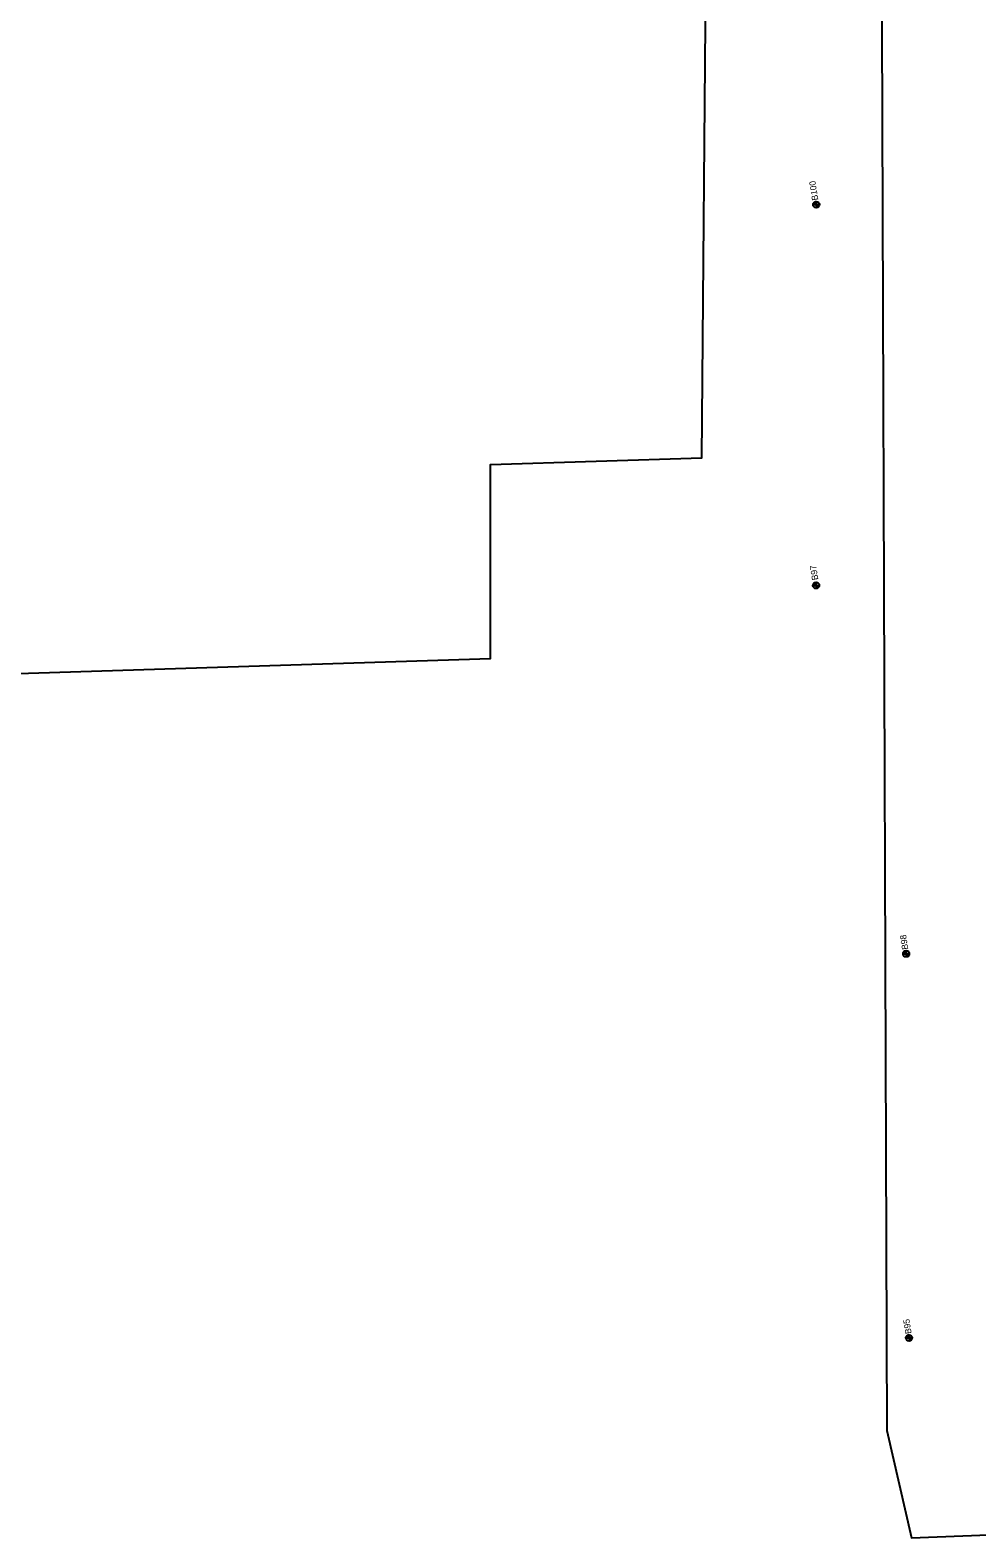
# Model space of a CAD drawing. Extents: x 331323 to 388339, y 121519 to 205315.
# Drawn here: x 354755 to 356257, y 180308 to 182703 of the extents above; entities that cross this region are included whole.
import ezdxf

# ---------------------------------------------------------------- set-up
doc = ezdxf.new("R2010")
doc.units = 0
for name, color, linetype in [('E_SOIL_BORE1 [KAPUR_CADDS_LEVELS]', 7, 'Continuous'), ('E_SOIL_BORE2 [KAPUR_CADDS_LEVELS]', 7, 'Continuous'), ('Level 21', 7, 'Continuous'), ('P_MARK', 7, 'Continuous')]:
    doc.layers.add(name, color=color, linetype=linetype)

msp = doc.modelspace()

# ---------------------------------------------------------------- linework, layer by layer
at = {"layer": 'Level 21'}
for points in [[(356105.1, 183006.3), (356114.3, 180479.1), (356153.7, 180308.5), (356397.8, 180318.1)], [(353557.1, 182916.5), (353547.6, 182701.3), (353533.4, 182581.6), (353525.2, 182506.3), (353462.8, 182406.1), (353416.3, 182333.8), (353341.3, 182220), (353327.7, 182131.7), (353320.6, 182067.3), (353306.1, 181966.7), (353328.2, 181715.1), (353337, 181619.1), (353349.1, 181504.5), (353365.8, 181335.5), (353376.4, 181288.1), (353386.3, 181245), (353405.7, 181167), (354162.4, 181174.2), (354327.4, 181348.1), (354335.3, 181668.3), (355485.3, 181704.9), (355485.4, 182013), (355820.8, 182023.7), (355827.8, 182838.2)]]:
    msp.add_lwpolyline(points, dxfattribs=at)
at = {"layer": 'P_MARK'}
for p, q in [((356002.3, 182430.8), (356002.3, 182420.8)), ((355997.3, 182425.8), (356007.3, 182425.8)), ((355997.1, 181821), (356007.1, 181821)), ((356002.1, 181826), (356002.1, 181816)), ((356140, 181236), (356150, 181236)), ((356145, 181241), (356145, 181231)), ((356149.6, 180631), (356149.6, 180621)), ((356144.6, 180626), (356154.6, 180626))]:
    msp.add_line(p, q, dxfattribs=at)
for centre in [(356002.3, 182425.8), (356002.1, 181821), (356145, 181236), (356149.6, 180626)]:
    msp.add_circle(centre, 5, dxfattribs=at)
for centre, radius, start, end in [((356002.3, 182425.8), 4.5, 89.9869, 179.9869), ((356002.3, 182425.8), 4, 89.9869, 179.9869), ((356002.3, 182425.8), 3.5, 89.9869, 179.9869), ((356002.3, 182425.8), 3, 89.9869, 179.9869), ((356002.3, 182425.8), 2.5, 89.9869, 179.9869), ((356002.3, 182425.8), 2, 89.9869, 179.9869), ((356002.3, 182425.8), 1.5, 89.9869, 179.9869), ((356002.3, 182425.8), 1, 89.9869, 179.9869), ((356002.3, 182425.8), 0.5, 89.9869, 179.9869), ((356002.3, 182425.8), 4.5, 269.9869, 359.9869), ((356002.3, 182425.8), 4, 269.9869, 359.9869), ((356002.3, 182425.8), 3.5, 269.9869, 359.9869), ((356002.3, 182425.8), 3, 269.9869, 359.9869), ((356002.3, 182425.8), 2.5, 269.9869, 359.9869), ((356002.3, 182425.8), 2, 269.9869, 359.9869), ((356002.3, 182425.8), 1.5, 269.9869, 359.9869), ((356002.3, 182425.8), 1, 269.9869, 359.9869), ((356002.3, 182425.8), 0.5, 269.9869, 359.9869), ((356002.1, 181821), 4.5, 89.9869, 179.9869), ((356002.1, 181821), 4, 89.9869, 179.9869), ((356002.1, 181821), 3.5, 89.9869, 179.9869), ((356002.1, 181821), 3, 89.9869, 179.9869), ((356002.1, 181821), 2.5, 89.9869, 179.9869), ((356002.1, 181821), 2, 89.9869, 179.9869), ((356002.1, 181821), 1.5, 89.9869, 179.9869), ((356002.1, 181821), 1, 89.9869, 179.9869), ((356002.1, 181821), 0.5, 89.9869, 179.9869), ((356002.1, 181821), 4.5, 269.9869, 359.9869), ((356002.1, 181821), 4, 269.9869, 359.9869), ((356002.1, 181821), 3.5, 269.9869, 359.9869), ((356002.1, 181821), 3, 269.9869, 359.9869), ((356002.1, 181821), 2.5, 269.9869, 359.9869), ((356002.1, 181821), 2, 269.9869, 359.9869), ((356002.1, 181821), 1.5, 269.9869, 359.9869), ((356002.1, 181821), 1, 269.9869, 359.9869), ((356002.1, 181821), 0.5, 269.9869, 359.9869), ((356145, 181236), 4.5, 89.9869, 179.9869), ((356145, 181236), 4, 89.9869, 179.9869), ((356145, 181236), 3.5, 89.9869, 179.9869), ((356145, 181236), 3, 89.9869, 179.9869), ((356145, 181236), 2.5, 89.9869, 179.9869), ((356145, 181236), 2, 89.9869, 179.9869), ((356145, 181236), 1.5, 89.9869, 179.9869), ((356145, 181236), 1, 89.9869, 179.9869), ((356145, 181236), 0.5, 89.9869, 179.9869), ((356145, 181236), 4.5, 269.9869, 359.9869), ((356145, 181236), 4, 269.9869, 359.9869), ((356145, 181236), 3.5, 269.9869, 359.9869), ((356145, 181236), 3, 269.9869, 359.9869), ((356145, 181236), 2.5, 269.9869, 359.9869), ((356145, 181236), 2, 269.9869, 359.9869), ((356145, 181236), 1.5, 269.9869, 359.9869), ((356145, 181236), 1, 269.9869, 359.9869), ((356145, 181236), 0.5, 269.9869, 359.9869), ((356149.6, 180626), 4.5, 89.9869, 179.9869), ((356149.6, 180626), 4, 89.9869, 179.9869), ((356149.6, 180626), 3.5, 89.9869, 179.9869), ((356149.6, 180626), 3, 89.9869, 179.9869), ((356149.6, 180626), 2.5, 89.9869, 179.9869), ((356149.6, 180626), 2, 89.9869, 179.9869), ((356149.6, 180626), 1.5, 89.9869, 179.9869), ((356149.6, 180626), 1, 89.9869, 179.9869), ((356149.6, 180626), 0.5, 89.9869, 179.9869), ((356149.6, 180626), 4.5, 269.9869, 359.9869), ((356149.6, 180626), 4, 269.9869, 359.9869), ((356149.6, 180626), 3.5, 269.9869, 359.9869), ((356149.6, 180626), 3, 269.9869, 359.9869), ((356149.6, 180626), 2.5, 269.9869, 359.9869), ((356149.6, 180626), 2, 269.9869, 359.9869), ((356149.6, 180626), 1.5, 269.9869, 359.9869), ((356149.6, 180626), 1, 269.9869, 359.9869), ((356149.6, 180626), 0.5, 269.9869, 359.9869)]:
    msp.add_arc(centre, radius, start, end, dxfattribs=at)

# ---------------------------------------------------------------- texts
at = {"layer": 'E_SOIL_BORE1 [KAPUR_CADDS_LEVELS]'}
for s, p in [('B97', (356005.7, 181830.2)), ('B98', (356148.5, 181243.4)), ('B95', (356153.7, 180633.1))]:
    msp.add_text(s, height=10, rotation=98.957, dxfattribs=at).set_placement(p)
at = {"layer": 'E_SOIL_BORE2 [KAPUR_CADDS_LEVELS]'}
msp.add_text('B100', height=10, rotation=98.957, dxfattribs=at).set_placement((356005.7, 182433.2))

doc.saveas('drawing.dxf')
